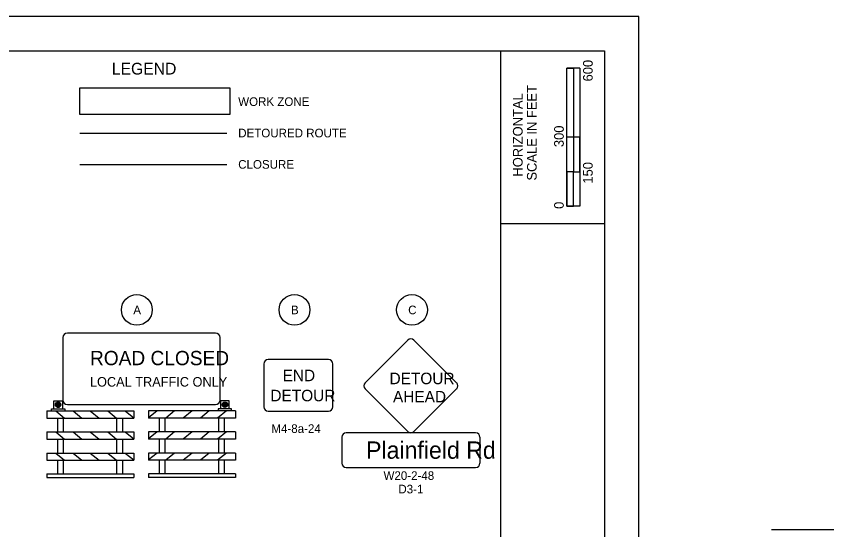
# Model space of a CAD drawing. Extents: x 0 to 42, y 0 to 22.
# Drawn here: x 24.96 to 36.8, y 14.52 to 21.95 of the extents above; entities that cross this region are included whole.
import ezdxf

# ---------------------------------------------------------------- set-up
doc = ezdxf.new("R2010")
doc.units = 0
for name, color, linetype in [('RW_P_Const_Limits', 7, 'Continuous'), ('SH_Border', 7, 'Continuous'), ('SH_Cut_Line', 7, 'Continuous'), ('SH_Data', 7, 'Continuous'), ('SH_Text', 7, 'Continuous'), ('SN_P_Signs', 7, 'Continuous'), ('SN_P_Text', 7, 'Continuous')]:
    doc.layers.add(name, color=color, linetype=linetype)

msp = doc.modelspace()

# ---------------------------------------------------------------- linework, layer by layer
at = {"layer": 'RW_P_Const_Limits'}
msp.add_lwpolyline([(28.056, 20.913), (25.877, 20.913), (25.877, 20.539), (28.056, 20.539)], close=True, dxfattribs=at)
at = {"layer": 'SH_Border'}
for p, q in [((31.977, 0.455), (31.977, 21.455)), ((31.977, 18.955), (33.477, 18.955))]:
    msp.add_line(p, q, dxfattribs=at)
msp.add_lwpolyline([(1.477, 21.455), (33.477, 21.455), (33.477, 0.455), (1.477, 0.455)], close=True, dxfattribs=at)
at = {"layer": 'SH_Cut_Line'}
msp.add_lwpolyline([(-0.023, -0.045), (33.977, -0.045), (33.977, 21.955), (-0.023, 21.955)], close=True, dxfattribs=at)
at = {"layer": 'SH_Data'}
for p, q in [((32.934, 19.205), (32.934, 21.205)), ((33.121, 21.205), (32.934, 21.205)), ((32.934, 20.205), (32.934, 21.205)), ((32.934, 21.205), (33.027, 21.205)), ((33.027, 21.205), (33.028, 21.205)), ((33.028, 21.205), (33.028, 20.205)), ((33.121, 21.205), (33.121, 19.205)), ((33.028, 20.205), (32.934, 20.205)), ((33.12, 20.205), (33.027, 20.205)), ((33.027, 20.205), (33.027, 19.705)), ((33.12, 19.705), (33.12, 20.205)), ((33.027, 19.705), (32.934, 19.705)), ((32.934, 19.705), (32.934, 19.205)), ((33.027, 19.205), (33.027, 19.705)), ((33.027, 19.705), (33.12, 19.705)), ((33.121, 19.205), (32.934, 19.205)), ((32.934, 19.205), (33.027, 19.205)), ((25.527, 16.332), (25.605, 16.332)), ((25.53, 16.344), (25.602, 16.344)), ((25.538, 16.357), (25.593, 16.357)), ((28.02, 16.332), (27.942, 16.332)), ((28.017, 16.344), (27.945, 16.344)), ((28.009, 16.357), (27.954, 16.357)), ((25.403, 16.239), (26.661, 16.239)), ((25.403, 16.239), (25.403, 16.136)), ((25.528, 16.319), (25.604, 16.319)), ((25.533, 16.307), (25.598, 16.307)), ((25.533, 16.239), (25.661, 16.136)), ((25.548, 16.294), (25.584, 16.294)), ((25.782, 16.239), (25.91, 16.136)), ((26.032, 16.239), (26.16, 16.136)), ((26.284, 16.239), (26.412, 16.136)), ((26.536, 16.239), (26.661, 16.138)), ((26.661, 16.239), (26.661, 16.136)), ((28.134, 16.239), (26.876, 16.239)), ((26.876, 16.239), (26.876, 16.136)), ((27.001, 16.239), (26.876, 16.138)), ((27.253, 16.239), (27.125, 16.136)), ((27.505, 16.239), (27.377, 16.136)), ((27.755, 16.239), (27.627, 16.136)), ((28.004, 16.239), (27.875, 16.136)), ((28.019, 16.319), (27.943, 16.319)), ((28.014, 16.307), (27.949, 16.307)), ((27.999, 16.294), (27.963, 16.294)), ((28.134, 16.239), (28.134, 16.136)), ((25.403, 16.136), (26.661, 16.136)), ((25.56, 15.935), (25.56, 16.136)), ((25.644, 15.935), (25.644, 16.136)), ((26.418, 15.935), (26.418, 16.136)), ((26.502, 15.935), (26.502, 16.136)), ((28.134, 16.136), (26.876, 16.136)), ((27.035, 15.935), (27.035, 16.136)), ((27.118, 15.935), (27.118, 16.136)), ((27.893, 15.935), (27.893, 16.136)), ((27.977, 15.935), (27.977, 16.136)), ((25.403, 15.935), (26.661, 15.935)), ((25.403, 15.935), (25.403, 15.831)), ((25.533, 15.935), (25.661, 15.831)), ((25.782, 15.935), (25.91, 15.831)), ((26.032, 15.935), (26.16, 15.831)), ((26.284, 15.935), (26.412, 15.831)), ((26.536, 15.935), (26.661, 15.834)), ((26.661, 15.935), (26.661, 15.831)), ((28.134, 15.935), (26.876, 15.935)), ((26.876, 15.935), (26.876, 15.831)), ((27.001, 15.935), (26.876, 15.834)), ((27.253, 15.935), (27.125, 15.831)), ((27.505, 15.935), (27.377, 15.831)), ((27.755, 15.935), (27.627, 15.831)), ((28.004, 15.935), (27.875, 15.831)), ((28.134, 15.935), (28.134, 15.831)), ((25.403, 15.831), (26.661, 15.831)), ((25.56, 15.63), (25.56, 15.831)), ((25.644, 15.63), (25.644, 15.831)), ((26.418, 15.63), (26.418, 15.831)), ((26.502, 15.63), (26.502, 15.831)), ((28.134, 15.831), (26.876, 15.831)), ((27.035, 15.63), (27.035, 15.831)), ((27.118, 15.63), (27.118, 15.831)), ((27.893, 15.63), (27.893, 15.831)), ((27.977, 15.63), (27.977, 15.831)), ((25.403, 15.63), (26.661, 15.63)), ((25.403, 15.63), (25.403, 15.526)), ((25.533, 15.63), (25.661, 15.526)), ((25.782, 15.63), (25.91, 15.526)), ((26.032, 15.63), (26.16, 15.526)), ((26.284, 15.63), (26.412, 15.526)), ((26.536, 15.63), (26.661, 15.529)), ((26.661, 15.63), (26.661, 15.526)), ((28.134, 15.63), (26.876, 15.63)), ((26.876, 15.63), (26.876, 15.526)), ((27.001, 15.63), (26.876, 15.529)), ((27.253, 15.63), (27.125, 15.526)), ((27.505, 15.63), (27.377, 15.526)), ((27.755, 15.63), (27.627, 15.526)), ((28.004, 15.63), (27.875, 15.526)), ((28.134, 15.63), (28.134, 15.526)), ((25.403, 15.526), (26.661, 15.526)), ((25.56, 15.326), (25.56, 15.526)), ((25.644, 15.326), (25.644, 15.526)), ((26.418, 15.326), (26.418, 15.526)), ((26.502, 15.326), (26.502, 15.526)), ((28.134, 15.526), (26.876, 15.526)), ((27.035, 15.326), (27.035, 15.526)), ((27.118, 15.326), (27.118, 15.526)), ((27.893, 15.326), (27.893, 15.526)), ((27.977, 15.326), (27.977, 15.526)), ((25.403, 15.326), (26.661, 15.326)), ((25.403, 15.326), (25.403, 15.277)), ((25.403, 15.277), (26.661, 15.277)), ((26.661, 15.326), (26.661, 15.277)), ((28.134, 15.326), (26.876, 15.326)), ((26.876, 15.326), (26.876, 15.277)), ((28.134, 15.277), (26.876, 15.277)), ((28.134, 15.326), (28.134, 15.277))]:
    msp.add_line(p, q, dxfattribs=at)
for points in [[(25.503, 16.271), (25.503, 16.386), (25.629, 16.386), (25.629, 16.271)], [(28.044, 16.271), (28.044, 16.386), (27.918, 16.386), (27.918, 16.271)], [(25.47, 16.239), (25.47, 16.271), (25.665, 16.271), (25.665, 16.239)], [(28.077, 16.239), (28.077, 16.271), (27.882, 16.271), (27.882, 16.239)]]:
    msp.add_lwpolyline(points, dxfattribs=at)
for centre in [(25.566, 16.329), (27.981, 16.329)]:
    msp.add_circle(centre, 0.0392, dxfattribs=at)
at = {"layer": 'SH_Text'}
for p, q in [((25.879, 20.264), (28.008, 20.264)), ((25.879, 19.81), (28.008, 19.81))]:
    msp.add_line(p, q, dxfattribs=at)
for centre in [(26.706, 17.703), (28.989, 17.703), (30.69, 17.703)]:
    msp.add_circle(centre, 0.223, dxfattribs=at)
at = {"layer": 'SN_P_Signs'}
msp.add_line((35.896, 14.52), (36.796, 14.52), dxfattribs=at)
for points in [[(25.635, 17.303), (25.635, 16.398)], [(27.846, 17.367), (25.7, 17.367)], [(27.911, 16.398), (27.911, 17.303)], [(30.012, 16.647), (30.63, 17.266)], [(30.719, 17.266), (31.337, 16.647)], [(29.48, 16.984), (28.61, 16.984)], [(28.545, 16.919), (28.545, 16.299)], [(29.545, 16.299), (29.545, 16.919)], [(30.63, 15.94), (30.012, 16.559)], [(31.337, 16.559), (30.719, 15.94)], [(25.7, 16.333), (27.846, 16.333)], [(28.61, 16.234), (29.48, 16.234)], [(29.674, 15.859), (29.674, 15.484)], [(31.612, 15.922), (29.737, 15.922)], [(31.674, 15.859), (31.674, 15.484)], [(29.737, 15.422), (31.612, 15.422)]]:
    msp.add_lwpolyline(points, dxfattribs=at)
for centre, radius, start, end in [((25.7, 17.303), 0.0646, 90, 180), ((27.846, 17.303), 0.0646, 0, 90), ((30.674, 17.222), 0.0625, 45, 135), ((28.61, 16.919), 0.065, 90, 180), ((29.48, 16.919), 0.065, 0, 90), ((30.056, 16.603), 0.0625, 135, 225), ((31.293, 16.603), 0.0625, 315, 45), ((25.7, 16.398), 0.0646, 180, 270), ((27.846, 16.398), 0.0646, 270, 0), ((28.61, 16.299), 0.065, 180, 270), ((29.48, 16.299), 0.065, 270, 0), ((29.737, 15.859), 0.0625, 90, 180), ((30.674, 15.984), 0.0625, 225, 315), ((31.612, 15.859), 0.0625, 0, 90), ((29.737, 15.484), 0.0625, 180, 270), ((31.612, 15.484), 0.0625, 270, 0)]:
    msp.add_arc(centre, radius, start, end, dxfattribs=at)

# ---------------------------------------------------------------- texts
at = {"layer": 'SH_Data'}
for s, p in [('600', (33.307, 21.012)), ('SCALE IN FEET', (32.495, 19.576)), ('HORIZONTAL', (32.292, 19.634)), ('300', (32.888, 20.061)), ('150', (33.307, 19.532)), ('0', (32.888, 19.166))]:
    msp.add_text(s, height=0.14, rotation=90, dxfattribs=at).set_placement(p)
at = {"layer": 'SH_Text'}
for s, height, p in [('LEGEND', 0.17, (26.344, 21.112)), ('WORK ZONE', 0.125, (28.174, 20.657)), ('DETOURED ROUTE', 0.125, (28.174, 20.202)), ('CLOSURE', 0.125, (28.174, 19.748)), ('A', 0.125, (26.655, 17.64)), ('B', 0.125, (28.938, 17.64)), ('C', 0.125, (30.635, 17.64))]:
    msp.add_text(s, height=height, dxfattribs=at).set_placement(p)
at = {"layer": 'SN_P_Signs'}
for s, height, p in [('ROAD CLOSED', 0.20685, (26.028, 16.902)), ('END', 0.1667, (28.817, 16.67)), ('LOCAL TRAFFIC ONLY', 0.1379, (26.027, 16.592)), ('DETOUR', 0.1667, (30.365, 16.627)), ('DETOUR', 0.1667, (28.64, 16.379)), ('AHEAD', 0.1667, (30.415, 16.363)), ('    Plainfield Rd', 0.25, (29.654, 15.547))]:
    msp.add_text(s, height=height, dxfattribs=at).set_placement(p)
at = {"layer": 'SN_P_Text'}
for s, p in [('M4-8a-24', (28.654, 15.921)), ('W20-2-48', (30.278, 15.24)), ('D3-1', (30.493, 15.045))]:
    msp.add_text(s, height=0.125, dxfattribs=at).set_placement(p)

doc.saveas('drawing.dxf')
